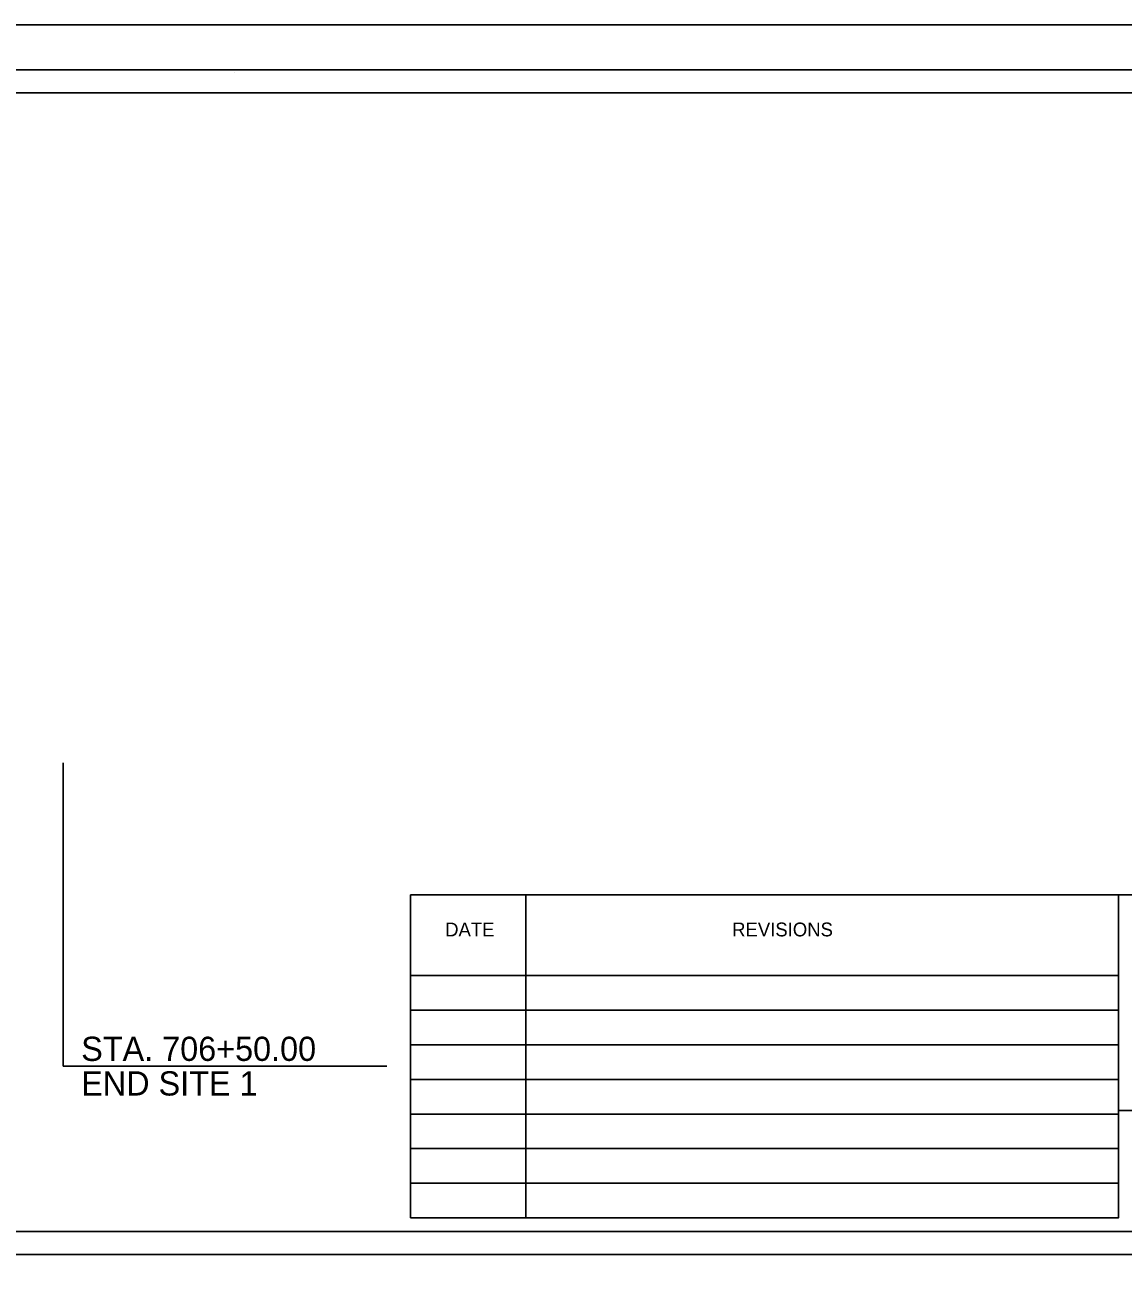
# Model space of a CAD drawing. Extents: x 814841 to 962585, y -174183 to 1802800.
# Drawn here: x 819784 to 820260, y 1802262 to 1802800 of the extents above; entities that cross this region are included whole.
import ezdxf

# ---------------------------------------------------------------- set-up
doc = ezdxf.new("R2010")
doc.units = 0
for name, color, linetype in [('Legend', 7, 'Continuous'), ('R_Border', 7, 'Continuous'), ('R_Border Notes', 7, 'Continuous'), ('R_Border Plan-Plan', 7, 'Continuous'), ('R_Detour Annot', 7, 'Continuous'), ('R_Draft', 7, 'Continuous'), ('R_No Plot', 7, 'Continuous')]:
    doc.layers.add(name, color=color, linetype=linetype)

msp = doc.modelspace()

# ---------------------------------------------------------------- linework, layer by layer
at = {"layer": 'Legend'}
msp.add_lwpolyline([(820257.98, 1802422.91), (820422.98, 1802422.91), (820422.98, 1802329.38), (820257.98, 1802329.38)], close=True, dxfattribs=at)
at = {"layer": 'R_Border'}
for p, q in [((819111.78, 1802780.6), (820692.68, 1802780.6)), ((819874.38, 1802779.3), (819874.38, 1802779.3)), ((819874.38, 1802779.3), (819874.38, 1802779.3))]:
    msp.add_line(p, q, dxfattribs=at)
at = {"layer": 'R_Border Notes'}
for p, q in [((820000.96, 1802422.91), (820257.98, 1802422.91)), ((820000.96, 1802422.91), (820000.96, 1802282.91)), ((819950.96, 1802387.91), (820257.98, 1802387.91)), ((819950.96, 1802372.91), (820257.98, 1802372.91)), ((819950.96, 1802357.91), (820257.98, 1802357.91)), ((819950.96, 1802342.91), (820257.98, 1802342.91)), ((819950.96, 1802327.91), (820257.98, 1802327.91)), ((819950.96, 1802312.91), (820257.98, 1802312.91)), ((819950.96, 1802297.91), (820257.98, 1802297.91)), ((819950.96, 1802282.91), (820257.98, 1802282.91))]:
    msp.add_line(p, q, dxfattribs=at)
msp.add_lwpolyline([(819950.96, 1802422.91), (820257.98, 1802422.91), (820257.98, 1802282.91), (819950.96, 1802282.91)], close=True, dxfattribs=at)
at = {"layer": 'R_Border Plan-Plan'}
msp.add_line((819111.78, 1802266.95), (820692.68, 1802266.95), dxfattribs=at)
at = {"layer": 'R_Draft'}
for p, q in [((819800.33, 1802348.68), (819800.33, 1802480.12)), ((819940.73, 1802348.68), (819800.33, 1802348.68))]:
    msp.add_line(p, q, dxfattribs=at)
at = {"layer": 'R_No Plot'}
for points in [[(819049.74, 1802800.08), (820716.44, 1802800.08), (820716.44, 1801733.39), (819049.74, 1801733.39)], [(820682.68, 1802276.95), (819121.78, 1802276.95), (819121.78, 1802770.6), (820369.48, 1802770.6), (820369.48, 1802721.2), (820457.18, 1802721.2), (820577.68, 1802721.2), (820577.68, 1802609.54), (820682.68, 1802609.54)], [(820682.68, 1802276.95), (819121.78, 1802276.95), (819121.78, 1802770.6), (820369.48, 1802770.6), (820369.48, 1802721.2), (820457.18, 1802721.2), (820577.68, 1802721.2), (820577.68, 1802609.54), (820682.68, 1802609.54)], [(820682.68, 1802276.95), (819121.78, 1802276.95), (819121.78, 1802770.6), (820369.48, 1802770.6), (820369.48, 1802721.2), (820457.18, 1802721.2), (820577.68, 1802721.2), (820577.68, 1802609.54), (820682.68, 1802609.54)], [(820682.68, 1802276.95), (819121.78, 1802276.95), (819121.78, 1802770.6), (820369.48, 1802770.6), (820369.48, 1802721.2), (820457.18, 1802721.2), (820577.68, 1802721.2), (820577.68, 1802609.54), (820682.68, 1802609.54)], [(820682.68, 1802276.95), (819121.78, 1802276.95), (819121.78, 1802770.6), (820369.48, 1802770.6), (820369.48, 1802721.2), (820457.18, 1802721.2), (820577.68, 1802721.2), (820577.68, 1802609.54), (820682.68, 1802609.54)], [(820682.68, 1802276.95), (819121.78, 1802276.95), (819121.78, 1802770.6), (820369.48, 1802770.6), (820369.48, 1802721.2), (820457.18, 1802721.2), (820577.68, 1802721.2), (820577.68, 1802609.54), (820682.68, 1802609.54)], [(819121.78, 1802770.6), (820369.48, 1802770.6), (820369.48, 1802721.2), (820457.18, 1802721.2), (820577.68, 1802721.2), (820577.68, 1802609.54), (820682.68, 1802609.54), (820682.68, 1801763.3), (819121.78, 1801763.3)], [(820682.68, 1802276.95), (819121.78, 1802276.95), (819121.78, 1802770.6), (820369.48, 1802770.6), (820369.48, 1802721.2), (820457.18, 1802721.2), (820577.68, 1802721.2), (820577.68, 1802609.54), (820682.68, 1802609.54)]]:
    msp.add_lwpolyline(points, close=True, dxfattribs=at)

# ---------------------------------------------------------------- texts
at = {"layer": 'Legend'}
for s, p in [('DATE', (819965.96, 1802404.91)), ('  REVISIONS', (820085.96, 1802404.91))]:
    msp.add_text(s, height=6, dxfattribs=at).set_placement(p)
at = {"layer": 'R_Detour Annot'}
for s, p in [('STA. 706+50.00', (819808.12, 1802350.93)), ('END SITE 1', (819808.12, 1802335.93))]:
    msp.add_text(s, height=10.5, dxfattribs=at).set_placement(p)

doc.saveas('drawing.dxf')
